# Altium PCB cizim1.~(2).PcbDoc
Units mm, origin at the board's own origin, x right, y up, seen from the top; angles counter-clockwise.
Board outline 152.4 x 101.6 mm, 2 copper layers (Top Layer, Bottom Layer); 15 components, 13 nets, 60 pads, 0 vias.
Unrouted connection lines stored in the file: 27.
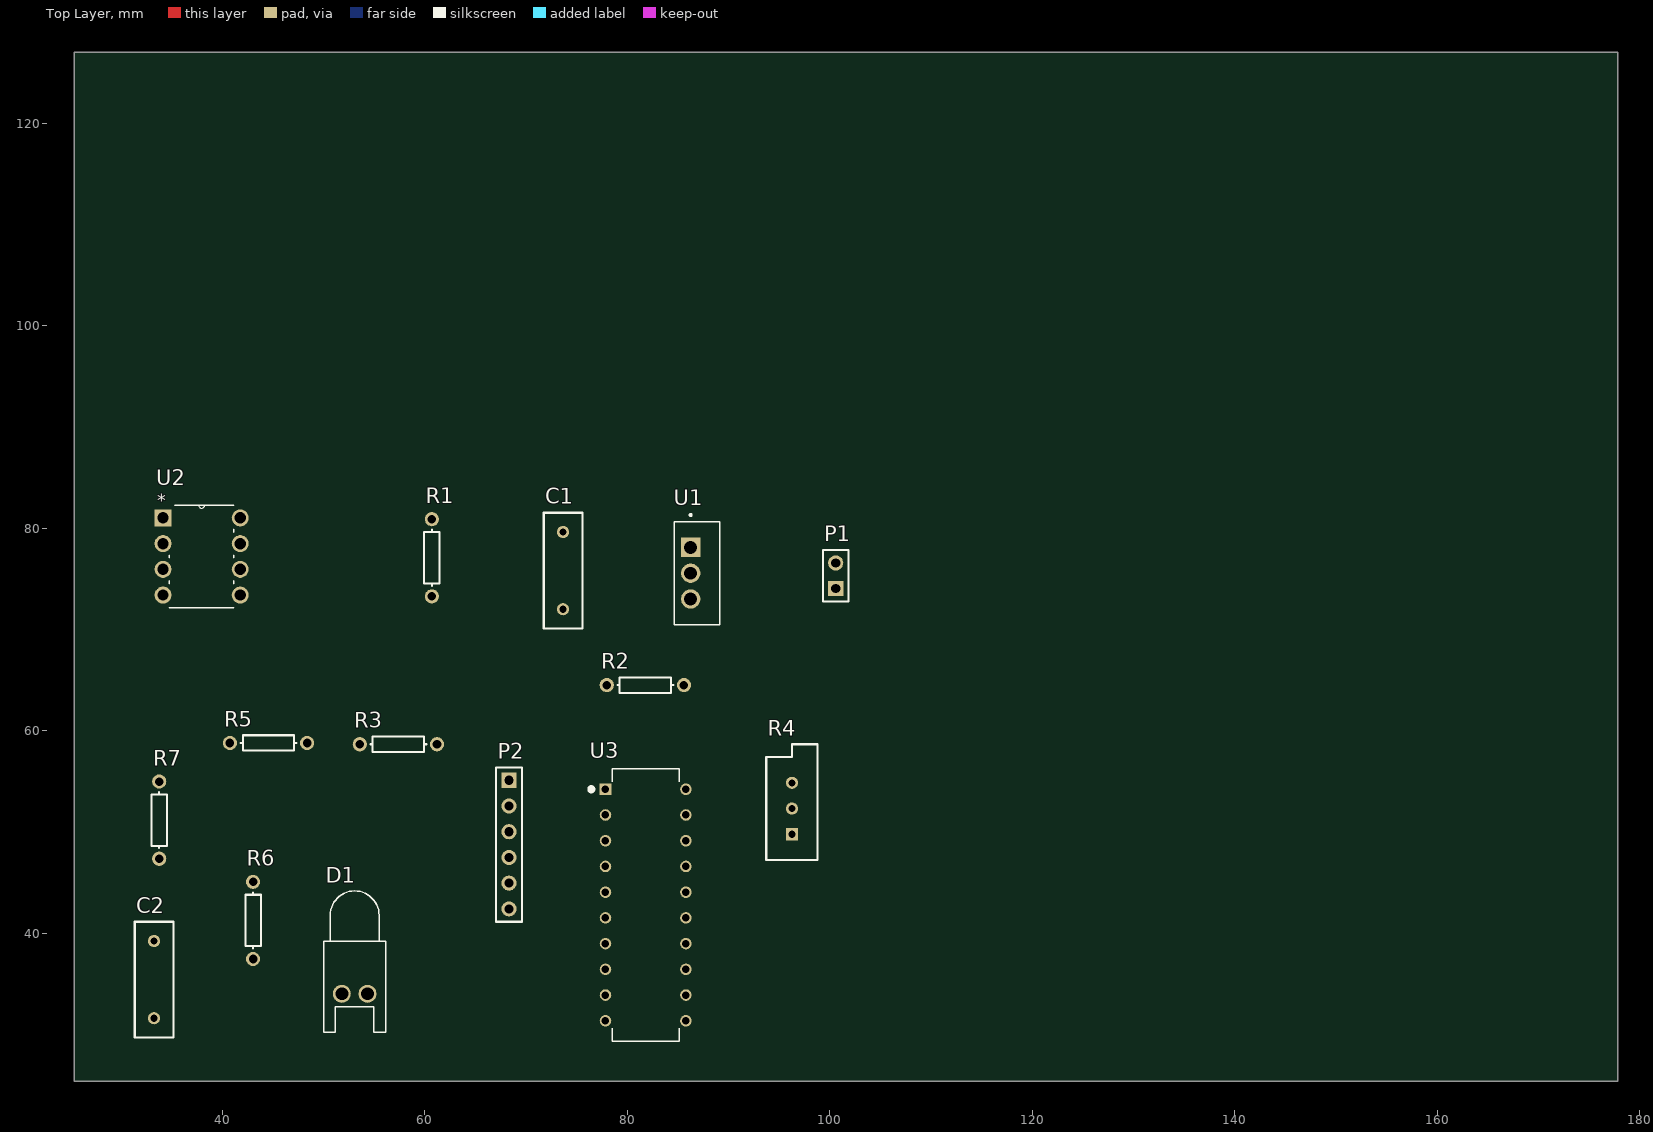
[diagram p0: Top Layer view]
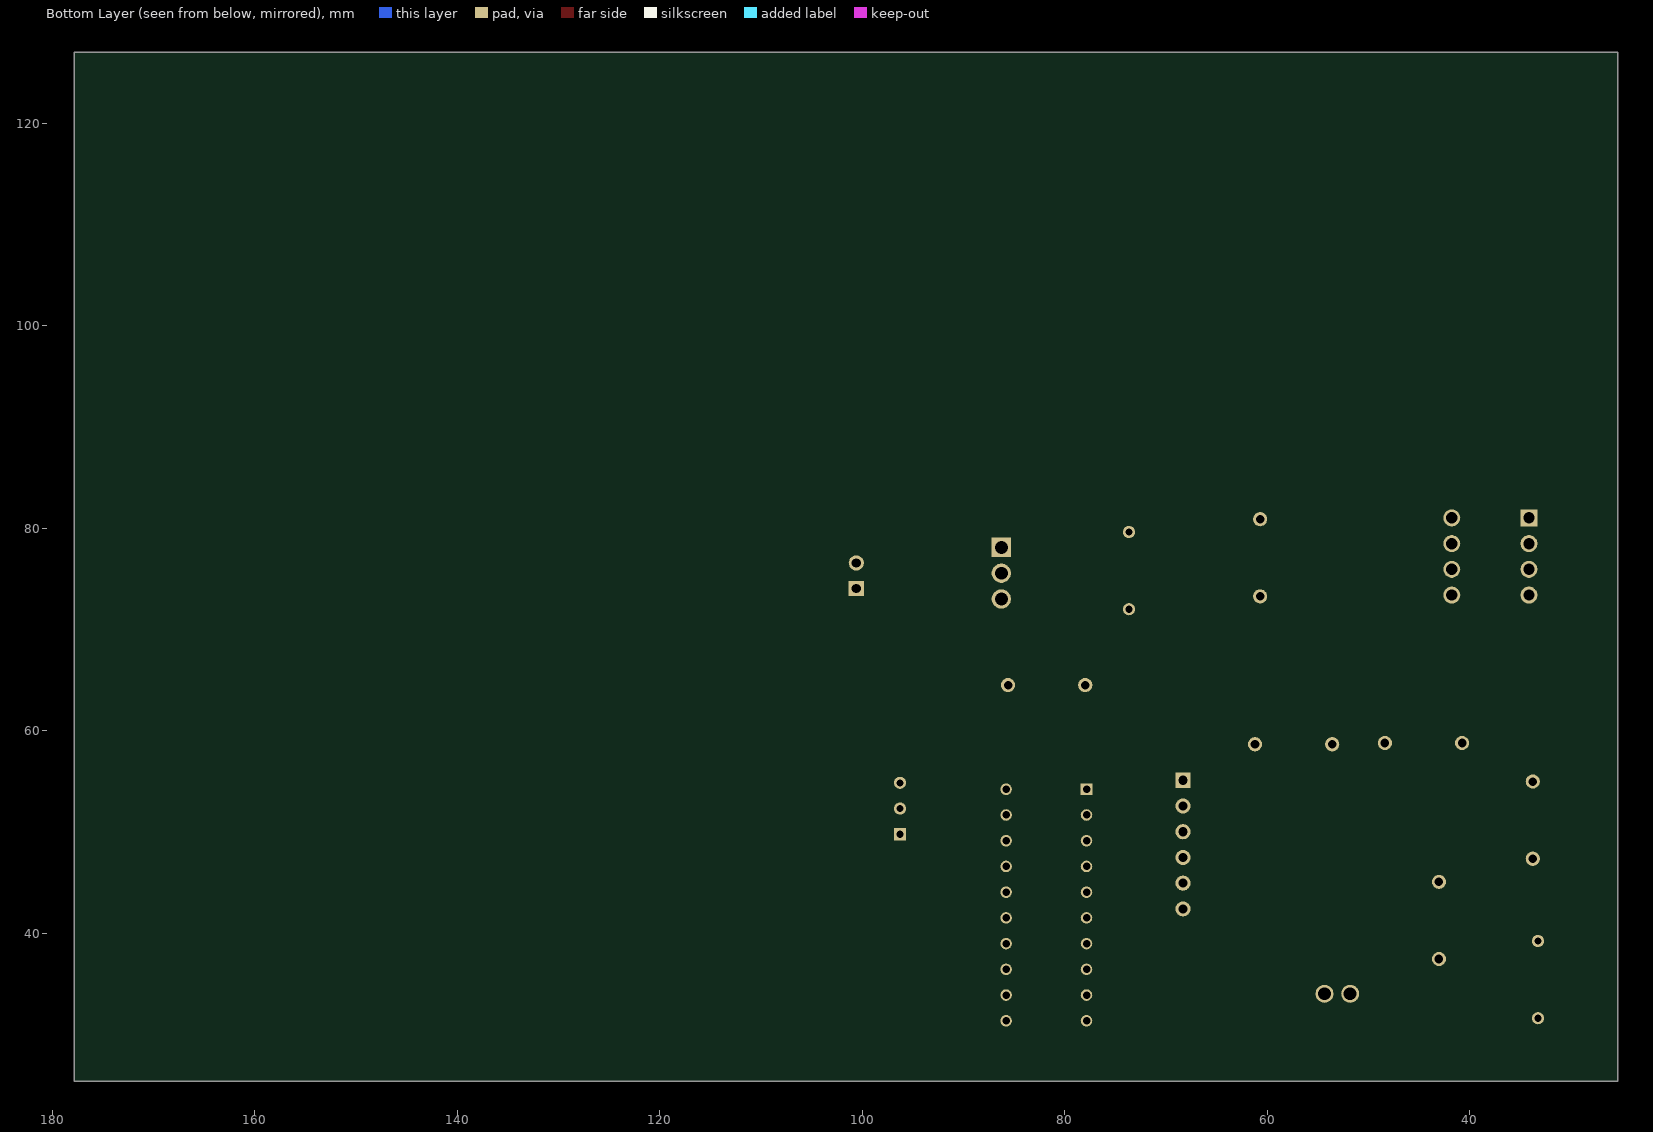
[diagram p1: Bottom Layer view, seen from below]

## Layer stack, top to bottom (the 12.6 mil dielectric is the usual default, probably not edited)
Top Solder: solder mask 0.0102, Solder Resist, Dk 3.5
Top Layer: signal copper 0.0356
Dielectric 1: dielectric 0.32, FR-4, Dk 4.8
Bottom Layer: signal copper 0.0356
Bottom Solder: solder mask 0.0102, Solder Resist, Dk 3.5

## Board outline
25.4,25.4 177.8,25.4 177.8,127 25.4,127

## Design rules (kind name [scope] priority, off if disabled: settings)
Clearance [All] p1: gap=0.254 ignorepadtopadclearanceinfootprint=FALSE except(0: Arc-Hole Track-Hole SMDPad-Hole THPad-Hole Via-Hole Fill-Hole Poly-Hole Region-Hole Text-Hole)
PolygonConnect [All] p1: connectstyle=Relief reliefconductorwidth=0.254 reliefentries=4 polygonreliefangle="90 Angle" airgapwidth=0.254
RoutingVias [All] p1: holewidth=0.711 width=1.27 viastyle="Through Hole" minholewidth=0.711 minwidth=1.27 maxholewidth=0.711 maxwidth=1.27
SolderMaskExpansion [All] p1: expansion=0.102 istentingtop=FALSE
Width [All] p1: maxlimit=0.254 minlimit=0.254 preferedwidth=0.254
30 further rules are at their usual default settings.

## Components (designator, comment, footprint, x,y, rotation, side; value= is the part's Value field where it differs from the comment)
C1 "Cap" RAD-0.3 73.66,75.819 r90 top value=1nF
C2 "Cap" RAD-0.3 33.274,35.433 r270 top value=1nF
D1 "LED0" LED-0 53.086,34.036 r180 top
P1 "Header 2" HDR1X2 100.584,74.041 r90 top
P2 "Header 6" HDR1X6 68.326,55.118 r270 top
R1 "Res1" AXIAL-0.3 60.706,77.089 r90 top value=100K
R2 "Res1" AXIAL-0.3 81.788,64.516 r180 top value=47K
R3 "Res1" AXIAL-0.3 57.404,58.674 r180 top value=1K
R4 "RPot" VR5 96.266,52.324 r90 top value=1K
R5 "Res1" AXIAL-0.3 44.577,58.801 r180 top value=100K
R6 "Res1" AXIAL-0.3 43.053,41.275 r90 top value=100K
R7 "Res1" AXIAL-0.3 33.782,51.181 r270 top value=47K
U1 "LD1117V33" TO255P1020X450X1968-3 86.868,75.565 r270 top
U2 "LM741CN" DIP254P762X508-8 41.783,73.406 r0 top
U3 "MSP430G2553IN20" DIP794W45P254L2692H508Q20 81.821,42.799 r0 top

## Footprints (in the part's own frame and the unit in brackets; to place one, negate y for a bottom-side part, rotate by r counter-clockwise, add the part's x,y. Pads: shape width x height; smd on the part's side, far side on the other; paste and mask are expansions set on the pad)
AXIAL-0.3 [mm] "Axial Device, Thru-Hole; 2 Leads; 0.3 in Pin Spacing"
  round 1.4 hole 0.85: 1(-3.81,0) 2(3.81,0)
  silkscreen extent -2.77,-0.76 2.77,0.76
DIP254P762X508-8 [mil]
  rect 66x66 hole 44: 1(-300,300)
  round 66 hole 44: 2(-300,200) 3(-300,100) 4(-300,0) 5(0,0) 6(0,100) 7(0,200) 8(0,300)
  silkscreen extent -275,-50 -25,350, body extent -189,-215 189,215, height 200
DIP794W45P254L2692H508Q20 [mm]
  rect 1.14x1.14 hole 0.74: 1(-3.97,11.43)
  round 1.14 hole 0.74: 2(-3.97,8.89) 3(-3.97,6.35) 4(-3.97,3.81) 5(-3.97,1.27) 6(-3.97,-1.27) 7(-3.97,-3.81) 8(-3.97,-6.35) 9(-3.97,-8.89) 10(-3.97,-11.43) 11(3.97,-11.43) 12(3.97,-8.89) 13(3.97,-6.35) 14(3.97,-3.81) 15(3.97,-1.27) 16(3.97,1.27) 17(3.97,3.81) 18(3.97,6.35) 19(3.97,8.89) 20(3.97,11.43)
  silkscreen extent -5.57,-13.46 3.3,13.46
HDR1X2 [mm] "Connector; Header; 2 Position"
  rect 1.5x1.5 hole 0.9: 1(0,0)
  round 1.5 hole 0.9: 2(2.54,0)
  silkscreen extent -1.27,-1.27 3.81,1.27
HDR1X6 [mm] "Connector; Header; 6 Position"
  rect 1.5x1.5 hole 0.9: 1(0,0)
  round 1.5 hole 0.9: 2(2.54,0) 3(5.08,0) 4(7.62,0) 5(10.16,0) 6(12.7,0)
  silkscreen extent -1.27,-1.27 13.97,1.27
LED-0 [mil] "LED; 2 Leads"
  round 70 hole 50: 1(50,0) 2(-50,0)
  silkscreen extent -120,-400 120,150
RAD-0.3 [mm] "Radial Cap, Thru-Hole; 2 Leads; 0.3 in Pin Spacing"
  round 1.2 hole 0.7: 1(-3.81,0) 2(3.81,0)
  silkscreen extent -5.71,-1.91 5.71,1.91
TO255P1020X450X1968-3 [mm]
  rect 1.91x1.91 / inner round 1.91 / far side rect 1.91x1.91 hole 1.27: 1(-2.55,-0.605)
  round 1.91 hole 1.27: 2(0,-0.605) 3(2.55,-0.605)
  silkscreen extent -5.85,-2.25 5.1,2.25, body extent -4.98,-1.76 4.98,2.69, height 19.68
VR5 [mm] "Thru-Hole; 3 Leads"
  rect 1.2x1.2 hole 0.7: 1(-2.54,0)
  round 1.2 hole 0.7: 2(0,0) 3(2.54,0)
  silkscreen extent -5.08,-2.54 6.35,2.54

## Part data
C1 C2: "Capacitor"
D1: "Typical INFRARED GaAs LED"
P1: "Header, 2-Pin"
P2: "Header, 6-Pin"
R1 R2 R3 R5 R6 R7: "Resistor"
R4: "Potentiometer"
U1: "Linear Voltage Regulator IC Positive Fixed 1 Output 800mA TO-220AB", Package="TO-220-3 ON Semiconductor"
U2: "General Purpose Amplifier 1 Circuit 8-DIP", Package="DIP-8 ON Semiconductor"
U3: "MSP430G2x53, MSP430G2x13 Mixed Signal Microcontroller 20-PDIP -40 to 85", Package=None

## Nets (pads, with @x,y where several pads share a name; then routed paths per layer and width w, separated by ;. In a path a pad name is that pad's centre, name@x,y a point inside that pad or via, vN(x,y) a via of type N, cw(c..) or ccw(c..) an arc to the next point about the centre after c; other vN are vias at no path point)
GND: C2.2 D1.2 P1.2 P2.6 R4.2 R6.1 R7.2 U1.1 U3.20
NetC1_1: C1.1 R1.1
NetC1_2: C1.2 C2.1 R6.2 U2.3
NetD1_1: D1.1 U3.5
NetP1_1: P1.1 U1.3 U2.7
NetP2_4: P2.4 U3.3
NetP2_5: P2.5 U3.4
NetR1_2: R1.2 R3.2 R5.1 U2.6
NetR2_1: R2.1 U3.16
NetR2_2: R2.2 U1.2 U3.1
NetR3_1: R3.1 R4.1
NetR4_3: R4.3 U3.2
NetR5_2: R5.2 R7.1 U2.2
pads on no net: P2.1 P2.2 P2.3 U2.1 U2.4 U2.5 U2.8 U3.6 U3.7 U3.8 U3.9 U3.10 U3.11 U3.12 U3.13 U3.14 U3.15 U3.17 U3.18 U3.19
